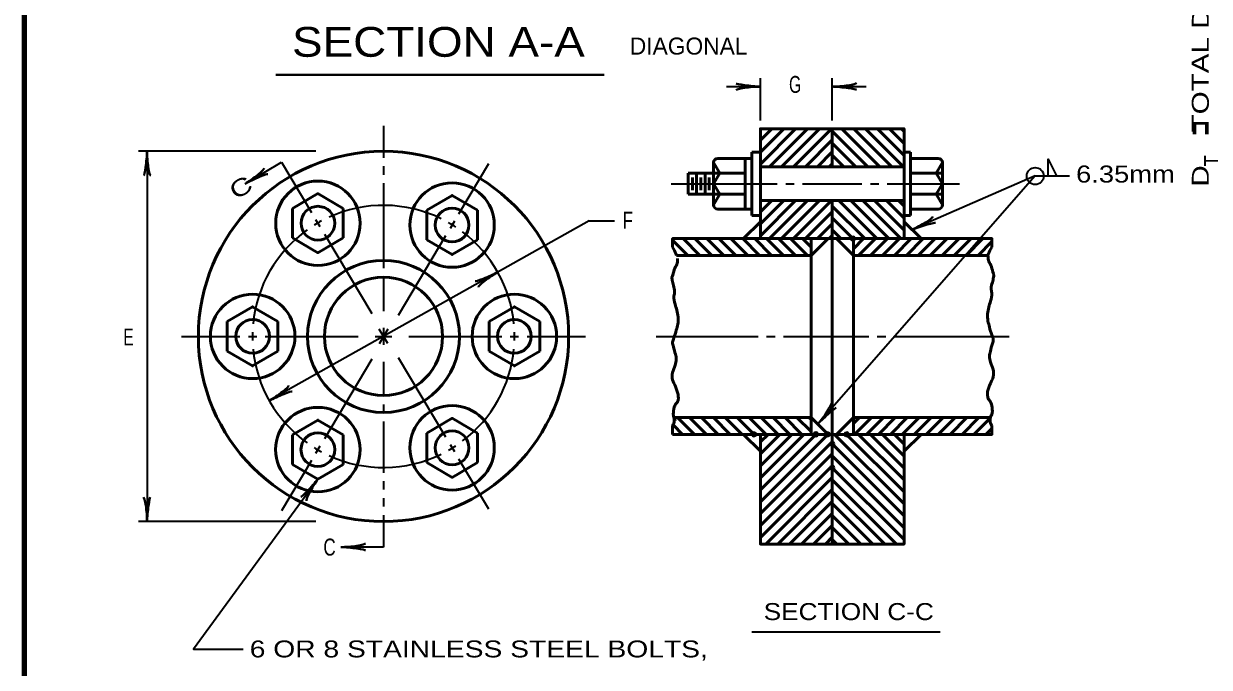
# Model space of a CAD drawing. Extents: x -29 to 827, y -14 to 530.
# Drawn here: x 28.3 to 196.8, y 158 to 249.5 of the extents above; entities that cross this region are included whole.
import ezdxf

# ---------------------------------------------------------------- set-up
doc = ezdxf.new("R2010")
doc.units = 0
doc.header["$LTSCALE"] = 0.97
doc.header["$PDMODE"] = 32
doc.header["$PDSIZE"] = 0.485
doc.layers.add('1', color=7, linetype='Continuous', lineweight=53)

msp = doc.modelspace()

# ---------------------------------------------------------------- linework, layer by layer
at = {"layer": '1', "lineweight": 40}
msp.add_line((64.1876, 242.1879), (110.8196, 242.1879), dxfattribs=at)
at = {"layer": '1', "lineweight": 35}
for p, q in [((133.0185, 235.7158), (133.0185, 241.7158)), ((143.2305, 235.7158), (143.2305, 241.7158)), ((128.2185, 240.5158), (133.0185, 240.5158)), ((143.2305, 240.5158), (148.0305, 240.5158)), ((69.8654, 231.3235), (44.6654, 231.3235)), ((45.8654, 231.3235), (45.8654, 178.7059)), ((59.8074, 226.7124), (64.9589, 229.7886)), ((64.9589, 229.7886), (69.2229, 222.6481)), ((79.4625, 229.2118), (79.4625, 227.9878)), ((94.4006, 229.5326), (90.135, 222.3931)), ((172.0704, 227.8165), (141.1707, 192.5524)), ((172.0704, 227.8165), (154.5641, 220.1998)), ((172.0704, 227.8165), (176.9184, 227.8165)), ((79.4625, 226.7878), (79.4625, 214.6918)), ((120.3585, 226.7158), (135.4185, 226.7158)), ((136.6185, 226.7158), (137.8185, 226.7158)), ((139.0185, 226.7158), (147.4425, 226.7158)), ((148.6425, 226.7158), (149.8425, 226.7158)), ((151.0425, 226.7158), (161.3002, 226.7158)), ((108.6784, 221.4293), (63.227, 195.8903)), ((69.8208, 221.6469), (70.4361, 220.6167)), ((70.1459, 221.0976), (70.1459, 221.1027)), ((89.5368, 221.3919), (88.9214, 220.3619)), ((108.6784, 221.4293), (112.3024, 221.4293)), ((71.0689, 219.5573), (77.8184, 208.2569)), ((88.2884, 219.3025), (81.5375, 208.0031)), ((79.4625, 213.4918), (79.4625, 208.6198)), ((80.0944, 203.9927), (78.8364, 206.0366)), ((80.0671, 206.0528), (78.8637, 203.9765)), ((79.4625, 206.2198), (79.4625, 203.8198)), ((50.7567, 205.0198), (59.073, 205.0198)), ((60.273, 205.0198), (61.473, 205.0198)), ((62.673, 205.0198), (75.8625, 205.0198)), ((78.2625, 205.0198), (80.6625, 205.0198)), ((83.0625, 205.0198), (96.2578, 205.0198)), ((97.4578, 205.0198), (98.6578, 205.0198)), ((99.8578, 205.0198), (108.1742, 205.0198)), ((118.1985, 205.0198), (132.6945, 205.0198)), ((133.8945, 205.0198), (135.1185, 205.0198)), ((136.3185, 205.0198), (148.4145, 205.0198)), ((149.6145, 205.0198), (150.8385, 205.0198)), ((152.0385, 205.0198), (168.3679, 205.0198)), ((77.8156, 201.7739), (71.0647, 190.4746)), ((79.4625, 201.4198), (79.4625, 196.5478)), ((81.5391, 202.0274), (88.2884, 190.7268)), ((79.4625, 195.3478), (79.4625, 194.1238)), ((79.4625, 192.9238), (79.4625, 185.6518)), ((70.4317, 189.4152), (69.8163, 188.3852)), ((88.9212, 189.6675), (89.5365, 188.6374)), ((69.2182, 187.384), (64.9525, 180.2446)), ((90.1346, 187.6361), (94.3997, 180.4963)), ((79.4625, 184.4518), (79.4625, 183.2518)), ((79.4625, 182.0278), (79.4625, 180.8278)), ((69.8654, 178.7059), (44.6654, 178.7059)), ((79.4625, 179.6038), (79.4625, 175.0678)), ((79.4625, 175.0678), (73.4145, 175.0678)), ((131.8065, 163.0198), (158.5425, 163.0198))]:
    msp.add_line(p, q, dxfattribs=at)
at = {"layer": '1'}
for p, q in [((133.0185, 232.9006), (134.6337, 234.5158)), ((133.0185, 231.2035), (136.3308, 234.5158)), ((133.0185, 229.5065), (138.0278, 234.5158)), ((134.3249, 229.1158), (139.7249, 234.5158)), ((136.0219, 229.1158), (141.4219, 234.5158)), ((137.719, 229.1158), (143.119, 234.5158)), ((149.9759, 229.1158), (144.5759, 234.5158)), ((151.673, 229.1158), (146.273, 234.5158)), ((153.37, 229.1158), (147.97, 234.5158)), ((153.4425, 230.7404), (149.6671, 234.5158)), ((153.4425, 232.4374), (151.3641, 234.5158)), ((153.4425, 234.1345), (153.0612, 234.5158)), ((139.4161, 229.1158), (143.2305, 232.9302)), ((148.2788, 229.1158), (143.2305, 234.1641)), ((131.8185, 231.2158), (131.8185, 222.2158)), ((131.8185, 231.2158), (133.0185, 231.2158)), ((141.1131, 229.1158), (143.2305, 231.2332)), ((146.5818, 229.1158), (143.2305, 232.4671)), ((153.4425, 231.2158), (154.3425, 231.2158)), ((154.3425, 231.2158), (154.3425, 222.2158)), ((126.3585, 229.7158), (126.3585, 223.7158)), ((126.9585, 230.3158), (131.8185, 230.3158)), ((130.8585, 230.3158), (130.8585, 223.1158)), ((133.0185, 229.1158), (133.0185, 224.3158)), ((142.8102, 229.1158), (143.2305, 229.5361)), ((144.8847, 229.1158), (143.2305, 230.77)), ((153.4425, 229.1158), (153.4425, 224.3158)), ((158.3002, 230.3158), (154.3425, 230.3158)), ((158.9002, 229.7158), (158.9002, 223.7158)), ((122.7585, 228.2158), (130.8585, 228.2158)), ((122.7585, 228.2158), (122.7585, 225.2158)), ((123.3585, 227.6158), (123.3585, 225.8158)), ((123.9585, 228.2158), (123.9585, 225.2158)), ((124.5585, 227.6158), (124.5585, 225.8158)), ((125.1585, 228.2158), (125.1585, 225.2158)), ((125.7585, 227.6158), (125.7585, 225.8158)), ((158.9002, 228.2158), (154.4002, 228.2158)), ((122.7585, 225.2158), (130.8585, 225.2158)), ((133.0185, 218.9158), (133.0185, 224.3158)), ((133.0185, 222.7025), (134.6318, 224.3158)), ((133.0185, 221.0055), (136.3288, 224.3158)), ((133.0185, 219.3084), (138.0259, 224.3158)), ((134.3229, 218.9158), (139.7229, 224.3158)), ((136.02, 218.9158), (141.42, 224.3158)), ((137.7171, 218.9158), (143.1171, 224.3158)), ((143.2305, 218.9158), (143.2305, 224.3158)), ((149.559, 218.9158), (144.159, 224.3158)), ((151.2561, 218.9158), (145.8561, 224.3158)), ((152.9531, 218.9158), (147.5531, 224.3158)), ((153.4425, 220.1235), (149.2502, 224.3158)), ((153.4425, 221.8205), (150.9472, 224.3158)), ((153.4425, 223.5176), (152.6443, 224.3158)), ((158.9002, 225.2158), (154.4002, 225.2158)), ((66.5459, 223.2027), (66.5459, 219.0027)), ((73.7459, 223.2027), (73.7459, 219.0027)), ((85.6117, 222.9478), (85.6117, 218.7478)), ((92.8117, 222.9478), (92.8117, 218.7478)), ((126.9585, 223.1158), (131.8185, 223.1158)), ((139.4141, 218.9158), (143.2305, 222.7322)), ((147.8619, 218.9158), (143.2305, 223.5472)), ((158.3002, 223.1158), (154.3425, 223.1158)), ((131.8185, 222.2158), (133.0185, 222.2158)), ((141.1112, 218.9158), (143.2305, 221.0351)), ((146.1649, 218.9158), (143.2305, 221.8502)), ((153.4425, 222.2158), (154.3425, 222.2158)), ((142.8082, 218.9158), (143.2305, 219.3381)), ((144.4678, 218.9158), (143.2305, 220.1531)), ((122.7263, 216.5158), (120.5505, 218.6916)), ((124.4233, 216.5158), (122.0233, 218.9158)), ((126.1204, 216.5158), (123.7204, 218.9158)), ((127.8174, 216.5158), (125.4174, 218.9158)), ((129.5145, 216.5158), (127.1145, 218.9158)), ((131.2116, 216.5158), (128.8116, 218.9158)), ((132.9086, 216.5158), (130.5086, 218.9158)), ((134.6057, 216.5158), (132.2057, 218.9158)), ((136.3027, 216.5158), (133.9027, 218.9158)), ((137.9998, 216.5158), (135.5998, 218.9158)), ((139.6968, 216.5158), (137.2968, 218.9158)), ((140.2185, 217.6912), (138.9939, 218.9158)), ((143.2305, 218.9158), (143.2305, 191.0998)), ((143.2305, 218.9158), (146.2425, 218.9158)), ((146.2425, 217.4838), (147.6745, 218.9158)), ((146.9715, 216.5158), (149.3715, 218.9158)), ((148.6686, 216.5158), (151.0686, 218.9158)), ((150.3656, 216.5158), (152.7656, 218.9158)), ((152.0627, 216.5158), (154.4627, 218.9158)), ((153.7598, 216.5158), (156.1598, 218.9158)), ((155.4568, 216.5158), (157.8568, 218.9158)), ((157.1539, 216.5158), (159.5539, 218.9158)), ((158.8509, 216.5158), (161.2509, 218.9158)), ((160.548, 216.5158), (162.948, 218.9158)), ((162.245, 216.5158), (164.645, 218.9158)), ((163.9421, 216.5158), (165.9105, 218.4842)), ((57.273, 207.1198), (57.273, 202.9198)), ((64.473, 207.1198), (64.473, 202.9198)), ((94.4578, 207.1198), (94.4578, 202.9198)), ((101.6578, 207.1198), (101.6578, 202.9198)), ((120.5505, 191.0998), (120.5505, 192.3238)), ((120.5505, 192.2998), (120.5505, 191.0998)), ((121.9459, 191.0998), (120.6096, 192.4361)), ((123.6429, 191.0998), (121.2429, 193.4998)), ((125.34, 191.0998), (122.94, 193.4998)), ((127.037, 191.0998), (124.637, 193.4998)), ((128.7341, 191.0998), (126.3341, 193.4998)), ((130.4312, 191.0998), (128.0312, 193.4998)), ((132.1282, 191.0998), (129.7282, 193.4998)), ((133.8253, 191.0998), (131.4253, 193.4998)), ((135.5223, 191.0998), (133.1223, 193.4998)), ((137.2194, 191.0998), (134.8194, 193.4998)), ((138.9164, 191.0998), (136.5164, 193.4998)), ((140.2185, 191.4948), (138.2135, 193.4998)), ((140.2185, 193.1919), (139.9106, 193.4998)), ((140.2185, 191.0998), (140.2185, 193.4998)), ((146.2425, 191.0998), (146.2425, 193.4998)), ((146.2425, 193.4998), (146.2425, 191.0998)), ((146.2425, 192.6405), (147.1018, 193.4998)), ((146.3989, 191.0998), (148.7989, 193.4998)), ((148.0959, 191.0998), (150.4959, 193.4998)), ((149.793, 191.0998), (152.193, 193.4998)), ((151.4901, 191.0998), (153.8901, 193.4998)), ((153.1871, 191.0998), (155.5871, 193.4998)), ((154.8842, 191.0998), (157.2842, 193.4998)), ((156.5812, 191.0998), (158.9812, 193.4998)), ((158.2783, 191.0998), (160.6783, 193.4998)), ((159.9753, 191.0998), (162.3753, 193.4998)), ((161.6724, 191.0998), (164.0724, 193.4998)), ((163.3695, 191.0998), (165.682, 193.4123)), ((165.9105, 191.0998), (165.9105, 192.2998)), ((66.5414, 186.8293), (66.5414, 191.0293)), ((73.7414, 186.8293), (73.7414, 191.0293)), ((85.6115, 187.0815), (85.6115, 191.2815)), ((92.8115, 187.0815), (92.8115, 191.2815)), ((133.0185, 191.0998), (120.5505, 191.0998)), ((133.0185, 190.0116), (134.1067, 191.0998)), ((133.0185, 188.3146), (135.8037, 191.0998)), ((133.0185, 186.6175), (137.5008, 191.0998)), ((133.0185, 184.9205), (139.1978, 191.0998)), ((133.0185, 183.2234), (140.8949, 191.0998)), ((133.0185, 181.5263), (142.592, 191.0998)), ((153.4425, 181.2241), (143.5668, 191.0998)), ((146.2425, 191.0998), (143.8305, 191.0998)), ((153.4425, 182.9211), (145.2638, 191.0998)), ((153.4425, 184.6182), (146.9609, 191.0998)), ((153.4425, 186.3153), (148.658, 191.0998)), ((153.4425, 188.0123), (150.355, 191.0998)), ((153.4425, 189.7094), (152.0521, 191.0998)), ((165.0665, 191.0998), (165.9105, 191.9438)), ((133.0185, 179.8293), (143.2305, 190.0413)), ((153.4425, 179.527), (143.2305, 189.739)), ((133.0185, 178.1322), (143.2305, 188.3442)), ((153.4425, 177.83), (143.2305, 188.042)), ((133.0185, 176.4352), (143.2305, 186.6472)), ((153.4425, 176.1329), (143.2305, 186.3449)), ((133.7802, 175.4998), (143.2305, 184.9501)), ((152.3786, 175.4998), (143.2305, 184.6479)), ((135.4772, 175.4998), (143.2305, 183.2531)), ((150.6815, 175.4998), (143.2305, 182.9508)), ((137.1743, 175.4998), (143.2305, 181.556)), ((148.9844, 175.4998), (143.2305, 181.2537)), ((138.8714, 175.4998), (143.2305, 179.8589)), ((147.2874, 175.4998), (143.2305, 179.5567)), ((140.5684, 175.4998), (143.2305, 178.1619)), ((145.5903, 175.4998), (143.2305, 177.8596)), ((142.2655, 175.4998), (143.2305, 176.4648)), ((143.8933, 175.4998), (143.2305, 176.1626))]:
    msp.add_line(p, q, dxfattribs=at)
at = {"layer": '1', "lineweight": 158}
msp.add_lwpolyline([(820.0407, 523.2545), (28.3407, 523.1545), (28.4407, -2.8455)], dxfattribs=at)
at = {"layer": '1', "lineweight": 35}
for points in [[(79.4625, 234.9478), (79.4625, 231.3238), (79.4625, 230.4118)], [(173.8944, 227.8165), (173.8944, 230.2165), (175.0944, 227.8165)], [(70.1414, 184.7293), (52.4689, 160.5702), (59.5325, 160.5702)]]:
    msp.add_lwpolyline(points, dxfattribs=at)
at = {"layer": '1'}
for points in [[(133.0185, 229.1158), (133.0185, 234.5158), (143.2305, 234.5158), (143.2305, 229.1158)], [(143.2305, 234.5158), (153.4425, 234.5158), (153.4425, 229.1158), (143.2305, 229.1158)], [(126.3585, 226.7158), (126.3585, 229.7158), (127.2585, 228.2158)], [(158.9002, 226.7158), (158.9002, 229.7158), (158.0002, 228.2158)], [(126.3585, 223.7158), (126.3585, 226.7158), (127.2585, 225.2158)], [(158.9002, 223.7158), (158.9002, 226.7158), (158.0002, 225.2158)], [(133.0185, 221.3158), (133.0185, 218.9158), (130.6065, 218.9158)], [(153.4425, 221.3158), (155.8545, 218.9158), (153.4425, 218.9158)], [(140.2185, 216.5158), (140.2185, 218.9158), (142.6305, 218.9158)], [(146.2425, 216.5158), (143.8305, 218.9158), (146.2425, 218.9158)], [(140.2185, 193.4998), (140.2185, 191.0998), (142.6305, 191.0998)], [(146.2425, 193.4998), (143.8305, 191.0998), (146.2425, 191.0998)], [(133.0185, 188.6998), (133.0185, 191.0998), (130.6065, 191.0998)], [(143.2305, 191.0998), (146.2425, 191.0998), (143.8305, 191.0998)], [(153.4425, 188.6998), (155.8545, 191.0998), (153.4425, 191.0998)]]:
    msp.add_lwpolyline(points, close=True, dxfattribs=at)
for points in [[(66.5459, 223.2027), (70.1459, 225.3027), (73.7459, 223.2027)], [(92.8117, 222.9478), (89.2117, 225.0478), (85.6117, 222.9478)], [(133.0185, 224.3158), (143.2305, 224.3158), (143.2305, 218.9158), (140.2185, 218.9158)], [(143.2305, 224.3158), (153.4425, 224.3158), (153.4425, 218.9158), (146.2425, 218.9158), (143.8305, 218.9158)], [(73.7459, 219.0027), (70.1459, 216.9027), (66.5459, 219.0027)], [(85.6117, 218.7478), (89.2117, 216.6478), (92.8117, 218.7478)], [(120.5505, 217.7158), (120.5505, 218.9158), (133.0185, 218.9158), (140.2185, 218.9158), (140.2185, 216.5158), (121.0755, 216.5158)], [(140.2185, 218.9158), (140.2185, 216.5158), (140.2185, 191.0998)], [(146.2425, 218.9158), (146.2425, 216.5158), (146.2425, 191.0998)], [(165.3589, 216.5158), (146.2425, 216.5158), (146.2425, 218.9158), (153.4425, 218.9158)], [(153.4425, 218.9158), (165.9105, 218.9158), (165.9105, 217.7158)], [(57.273, 207.1198), (60.873, 209.2198), (64.473, 207.1198)], [(101.6578, 207.1198), (98.0578, 209.2198), (94.4578, 207.1198)], [(64.473, 202.9198), (60.873, 200.8198), (57.273, 202.9198)], [(94.4578, 202.9198), (98.0578, 200.8198), (101.6578, 202.9198)], [(73.7414, 191.0293), (70.1414, 193.1293), (66.5414, 191.0293)], [(85.6115, 191.2815), (89.2115, 193.3815), (92.8115, 191.2815)], [(120.735, 193.4998), (140.2185, 193.4998), (140.2185, 191.0998), (133.0185, 191.0998), (130.6065, 191.0998)], [(146.2425, 191.0998), (146.2425, 193.4998), (165.7013, 193.4998)], [(165.9105, 192.3238), (165.9105, 191.0998), (153.4425, 191.0998), (146.2425, 191.0998)], [(143.2305, 191.0998), (143.2305, 175.4998), (133.0185, 175.4998), (133.0185, 180.8998), (133.0185, 185.6998), (133.0185, 191.0998), (140.2185, 191.0998), (142.6305, 191.0998)], [(143.2305, 191.0998), (140.2185, 191.0998), (143.2305, 191.0998)], [(143.2305, 185.6998), (143.2305, 191.0998), (146.2425, 191.0998), (143.8305, 191.0998)], [(146.2425, 191.0998), (153.4425, 191.0998), (153.4425, 185.6998), (153.4425, 180.8998), (153.4425, 175.4998), (143.2305, 175.4998), (143.2305, 191.0998), (143.2305, 185.6998)], [(92.8115, 187.0815), (89.2115, 184.9815), (85.6115, 187.0815)], [(66.5414, 186.8293), (70.1414, 184.7293), (73.7414, 186.8293)]]:
    msp.add_lwpolyline(points, dxfattribs=at)
at = {"layer": '1', "lineweight": 35}
msp.add_circle((172.0736, 227.8082), 1.2096, dxfattribs=at)
at = {"layer": '1'}
for centre, radius in [((70.1459, 221.0976), 6), ((89.2117, 220.8427), 6), ((70.1459, 221.1027), 2.4), ((89.2117, 220.8478), 2.4), ((79.4654, 205.0147), 10.8), ((79.4654, 205.0147), 8.4), ((60.873, 205.0147), 6), ((98.0578, 205.0147), 6), ((60.873, 205.0198), 2.4), ((98.0578, 205.0198), 2.4), ((70.1414, 188.9344), 6), ((89.2115, 189.1866), 6), ((70.1414, 188.9293), 2.4), ((89.2115, 189.1815), 2.4)]:
    msp.add_circle(centre, radius, dxfattribs=at)
for centre, radius, start, end in [((79.4654, 205.0147), 26.3088, 90, 180), ((79.4654, 205.0147), 26.3088, 0, 90), ((126.9585, 229.7158), 0.6, 90, 180), ((158.3002, 229.7158), 0.6, 0, 90), ((126.9585, 223.7158), 0.6, 180, 270), ((158.3002, 223.7158), 0.6, 270, 0), ((79.4655, 205.0148), 26.3088, 180, 270), ((79.4654, 205.0147), 26.3088, 270, 0)]:
    msp.add_arc(centre, radius, start, end, dxfattribs=at)
at = {"layer": '1', "lineweight": 35}
for start, end in [(63.9238, 114.55014), (118.23817, 121.93056), (56.53992, 60.2321), (125.62196, 174.44824), (5.55176, 52.85186), (178.13834, 181.83026), (358.16974, 1.86166), (185.52054, 234.36214), (307.14716, 354.47946), (238.05385, 241.74603), (299.7669, 303.45929), (245.43416, 296.07544)]:
    msp.add_arc((79.4654, 205.0147), 18.6263, start, end, dxfattribs=at)
at = {"layer": '1', "lineweight": 40}
for centre, major_axis, ratio, start_param, end_param in [((131.6739, 240.7697), (2.1077, -0.2108), 0.07063, 3.14071475, 5.41810995), ((131.6739, 240.7697), (2.1077, -0.2108), 0.07063, 3.14071475, 5.41810995), ((144.5399, 240.8474), (-2.1428, -0.1874), 0.122415, 0.89635335, 3.14159265), ((131.7091, 240.1842), (2.1428, 0.1874), 0.122415, 0.89635335, 3.14159265), ((131.7091, 240.1842), (2.1428, 0.1874), 0.122415, 0.89635335, 3.14159265), ((144.5751, 240.2619), (-2.1077, 0.2108), 0.07063, 3.14071475, 5.41810995), ((45.6115, 229.9789), (0.2108, 2.1077), 0.07063, 3.14071475, 5.41810995), ((45.6115, 229.9789), (0.2108, 2.1077), 0.07063, 3.14071475, 5.41810995), ((46.197, 230.0141), (-0.1874, 2.1428), 0.122415, 0.89635335, 3.14159265), ((46.197, 230.0141), (-0.1874, 2.1428), 0.122415, 0.89635335, 3.14159265), ((60.7617, 227.6684), (-1.7437, -1.2595), 0.122415, 0.89635335, 3.14159265), ((61.092, 227.1838), (1.9177, 0.8997), 0.07063, 6.28230741, 8.55970261), ((155.6325, 221.0262), (-1.8902, -1.0267), 0.122415, 0.89635335, 3.14159265), ((155.6325, 221.0262), (-1.8902, -1.0267), 0.122415, 0.89635335, 3.14159265), ((155.8984, 220.5034), (-2.0168, -0.6476), 0.07063, 3.14071475, 5.41810995), ((155.8984, 220.5034), (-2.0168, -0.6476), 0.07063, 3.14071475, 5.41810995), ((94.4073, 213.7016), (-1.9408, -0.8487), 0.07063, 6.28230741, 8.55970261), ((94.4073, 213.7016), (-1.9408, -0.8487), 0.07063, 6.28230741, 8.55970261), ((94.7247, 213.2084), (1.7763, 1.213), 0.122415, 0.89635335, 3.14159265), ((94.7247, 213.2084), (1.7763, 1.213), 0.122415, 0.89635335, 3.14159265), ((64.2062, 196.8208), (-1.7763, -1.213), 0.122415, 0.89635335, 3.14159265), ((64.5236, 196.3276), (1.9408, 0.8487), 0.07063, 6.28230741, 8.55970261), ((141.7843, 193.7558), (-1.2713, -1.7352), 0.122415, 0.89635335, 3.14159265), ((142.2478, 193.3964), (1.5476, 1.4464), 0.07063, 6.28230741, 8.55970261), ((69.1426, 183.794), (1.4145, 1.5767), 0.07063, 3.14071475, 5.41810995), ((69.6359, 183.4767), (1.1139, 1.8401), 0.122415, 0.89635335, 3.14159265), ((45.5338, 180.0153), (0.1874, -2.1428), 0.122415, 0.89635335, 3.14159265), ((46.1193, 180.0505), (-0.2108, -2.1077), 0.07063, 3.14071475, 5.41810995), ((74.7373, 175.4113), (-2.16, -0.1889), 0.122415, 0.89635335, 3.14159265), ((74.7728, 174.8212), (-2.1246, 0.2125), 0.07063, 3.14071475, 5.41810995)]:
    msp.add_ellipse(centre, major_axis=major_axis, ratio=ratio, start_param=start_param, end_param=end_param, dxfattribs=at)
at = {"layer": '1'}
for points in [[(121.0761, 216.5183), (121.0065, 216.7558), (120.5505, 217.7158)], [(165.9105, 217.7158), (165.4305, 216.7558), (165.3585, 216.5192)], [(121.2617, 216.0815), (121.1919, 215.4088), (120.8559, 214.7128), (120.5679, 213.7288), (120.4479, 213.2728), (120.4959, 213.0088), (120.6639, 212.2408), (120.8319, 211.4008), (120.7359, 210.7528), (120.9039, 209.5768), (121.1439, 208.7608), (121.2879, 206.7688), (121.0719, 205.9048), (120.7359, 204.8008), (120.5439, 204.1768), (120.6639, 203.5528), (120.9519, 202.4728), (121.0719, 201.7768), (120.9039, 200.9128), (120.5439, 199.8808), (120.5439, 198.8488), (120.9519, 197.8888), (121.3119, 196.7608), (121.2399, 195.7288), (120.9759, 195.3688), (120.6879, 194.4568), (120.7359, 193.4968), (120.9039, 193.1368), (120.9198, 193.0693)], [(165.3583, 216.5183), (165.4305, 215.8438), (165.7665, 215.1478), (166.0545, 214.1638), (166.1745, 213.7078), (166.1505, 213.4438), (165.9825, 212.6758), (165.8145, 211.8358), (165.8865, 211.1878), (165.7185, 210.0118), (165.4785, 209.1958), (165.3585, 207.2038), (165.5745, 206.3398), (165.8865, 205.2358), (166.1025, 204.6118), (165.9825, 203.9878), (165.6945, 202.9078), (165.5745, 202.2118), (165.7185, 201.3478), (166.1025, 200.3158), (166.1025, 199.2838), (165.6945, 198.3238), (165.3105, 197.1958), (165.4065, 196.1638), (165.6465, 195.8038), (165.9345, 194.8918), (165.8865, 193.9318), (165.7185, 193.5718), (165.7028, 193.5079)], [(120.5505, 192.3238), (120.7185, 192.6598), (120.7353, 193.5002)], [(165.7016, 193.503), (165.7185, 192.6598), (165.9105, 192.3238)]]:
    msp.add_spline(points, degree=3, dxfattribs=at)
for p in [(146.1649, 218.9158), (132.1282, 191.0998), (140.8949, 191.0998), (142.592, 191.0998), (145.2638, 191.0998), (143.2305, 189.739), (143.2305, 186.3449)]:
    msp.add_point(p, dxfattribs=at)

# ---------------------------------------------------------------- texts
for s, height, rotation, width, p in [('D    TOTAL DEPTH', 2.419, 90, 1.3, (196.7396, 226.2958)), ('=', 4.8, 90, 0.55, (197.8795, 233.5806)), ('T', 2.419, 90, 0.8, (198.4916, 229.1758)), ('C', 2.4, 30.843, 1.35, (58.4644, 224.3657))]:
    msp.add_text(s, height=height, rotation=rotation, dxfattribs=dict(at, width=width)).set_placement(p)
for s, height, width, p in [('SECTION A-A', 4.234, 1.15, (66.4676, 244.7559)), ('G', 2.4, 0.7, (137.0869, 239.6297)), ('6.35mm', 2.419, 1.2, (177.8784, 226.8805)), ('F', 2.4, 0.75, (113.4307, 220.323)), ('E', 2.4, 0.7, (42.4877, 203.7336)), ('C', 2.419, 0.75, (70.9185, 173.8678)), ('SECTION C-C', 2.419, 1.15, (133.4865, 164.6998)), ('6 OR 8 STAINLESS STEEL BOLTS,', 2.4, 1.25, (60.4538, 159.3991))]:
    msp.add_text(s, height=height, dxfattribs=dict(at, width=width)).set_placement(p)
msp.add_text('DIAGONAL', height=2.419, dxfattribs=at).set_placement((114.4676, 245.0679))

doc.saveas('drawing.dxf')
